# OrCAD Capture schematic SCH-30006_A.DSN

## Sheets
1 1. TITLE PAGE: title: FRDM33926PNBEVM; rev: A; company: Freescale Semiconductor; note: SCH-30006 PDF: SPF-30006; note: 6501 William Cannon Drive West; note: Austin, TX 78735-8598
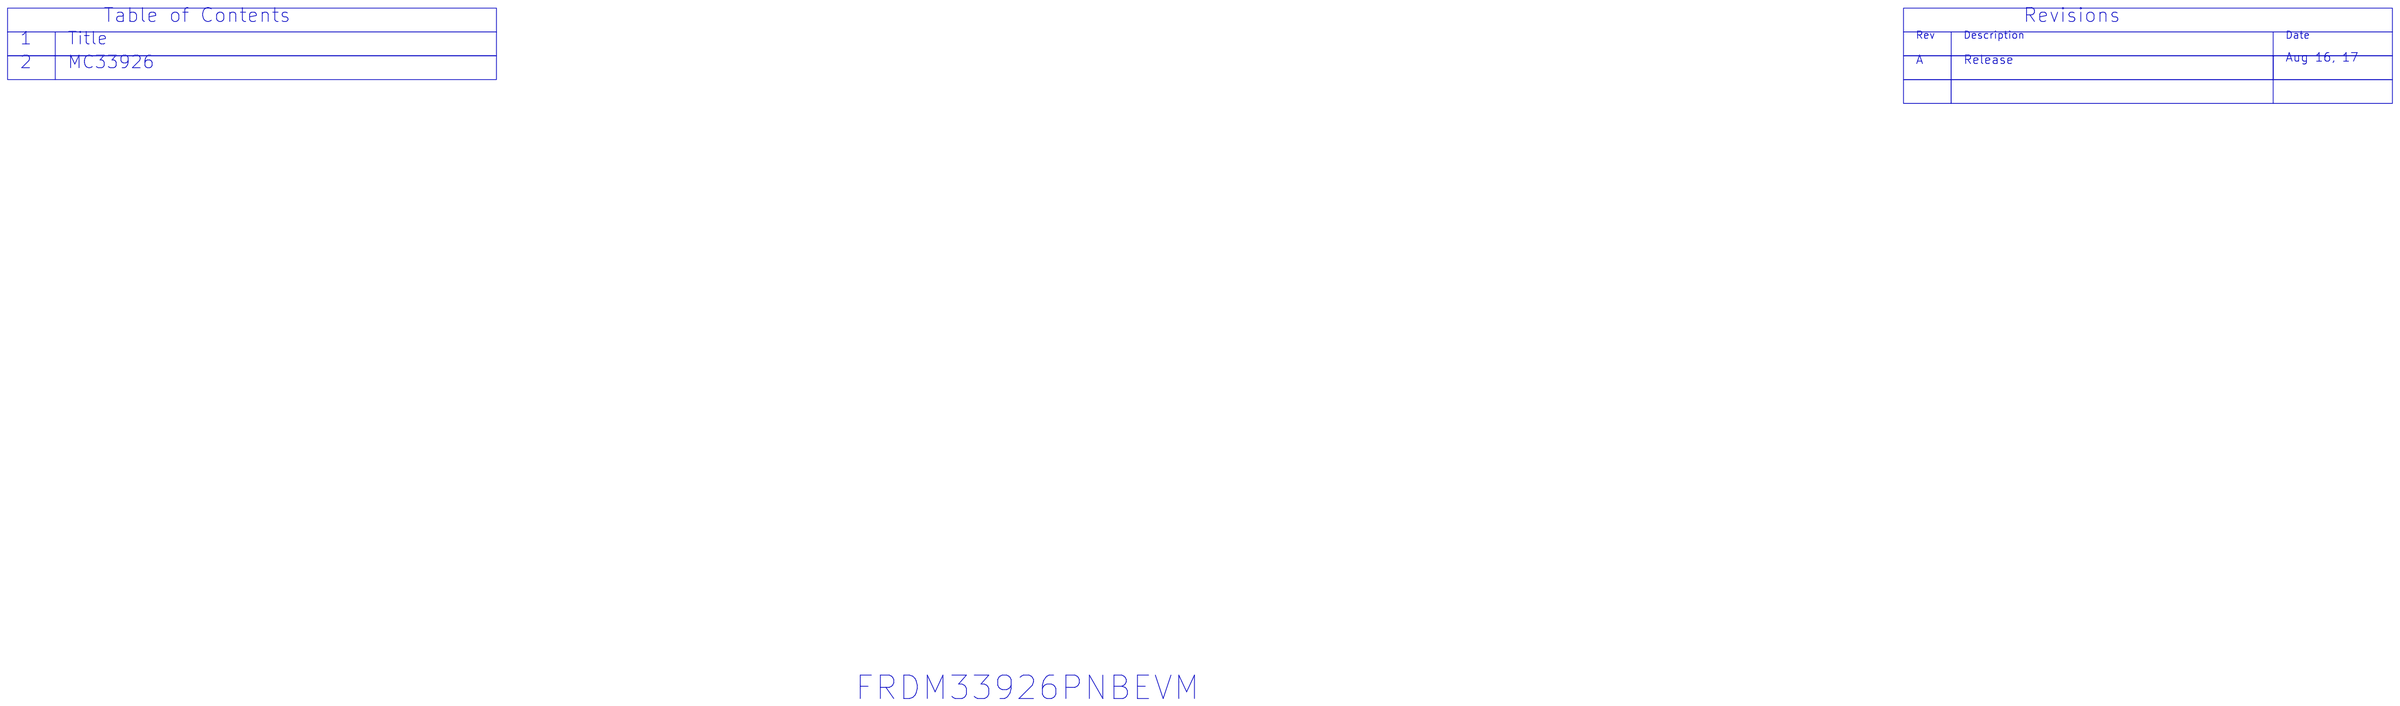
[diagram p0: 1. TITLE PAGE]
2 2. MC33926: size C
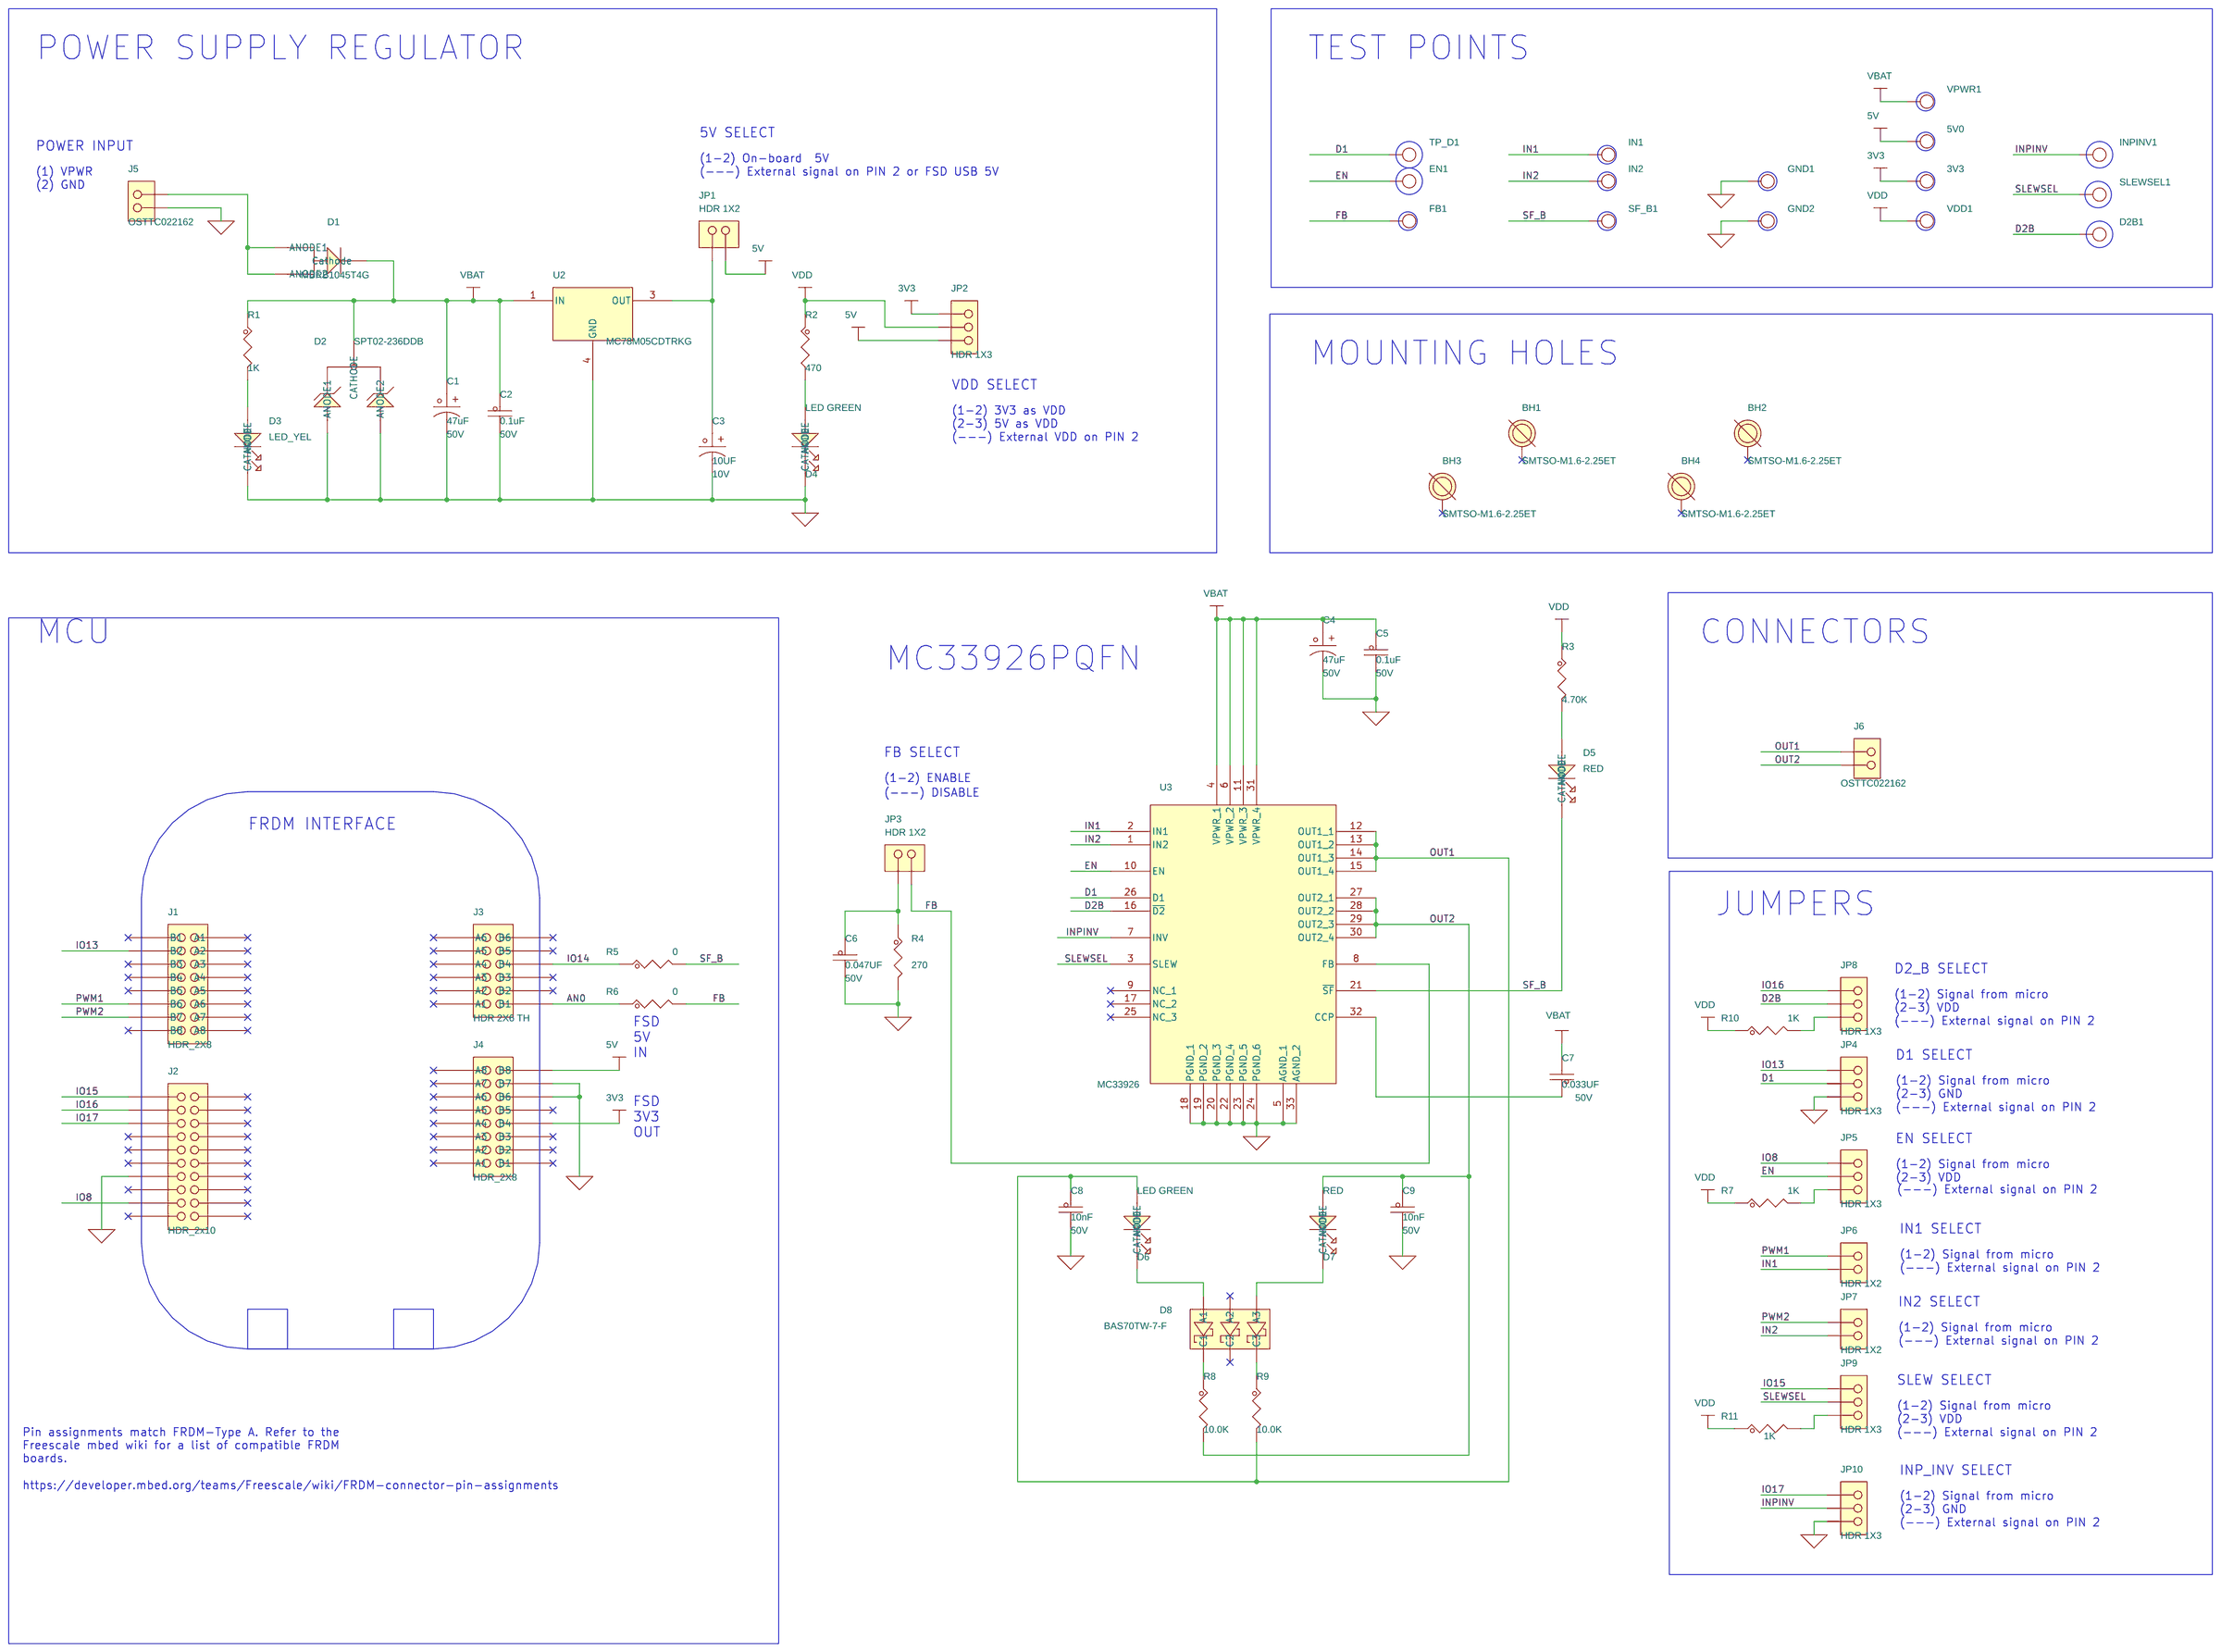
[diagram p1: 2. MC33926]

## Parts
3V3  TEST POINT RED  [TEST_LOOP]
5V0  TEST POINT RED  [TEST_LOOP]
BH1  SMTSO-M1.6-2.25ET  [MH194-116T]
BH2  SMTSO-M1.6-2.25ET  [MH194-116T]
BH3  SMTSO-M1.6-2.25ET  [MH194-116T]
BH4  SMTSO-M1.6-2.25ET  [MH194-116T]
C1  47uF  [cce10_3x10_3]
C2  0.1uF  [CC0603_OV]
C3  10UF  [CASE_A]
C4  47uF  [cce10_3x10_3]
C5  0.1uF  [CC0603_OV]
C6  0.047UF  [CC0805_OV]
C7  0.033UF  [CC0603_OV]
C8  10nF  [CC0603_OV]
C9  10nF  [CC0603_OV]
D1  MBRB1045T4G  [d2pak_b]
D2  SPT02-236DDB  [diode3_uqfn_sm]
D2B1  TEST POINT BLUE  [TEST_LOOP]
D3  LED_YEL  [LED_0603]
D4  LED GREEN  [LED_0603]
D5  RED  [0603LED]
D6  LED GREEN  [LED_0603]
D7  RED  [0603LED]
D8  BAS70TW-7-F  [sc70-6]
EN1  TEST POINT WHITE  [TEST_LOOP]
FB1  TEST POINT ORANGE  [TEST_LOOP]
GND1  TEST POINT BLACK  [TEST_LOOP]
GND2  TEST POINT BLACK  [TEST_LOOP]
IN1  TEST POINT BLUE  [TEST_LOOP]
IN2  TEST POINT BLUE  [TEST_LOOP]
INPINV1  TEST POINT BLUE  [TEST_LOOP]
J1  HDR_2X8  [HDR208]
J2  HDR_2x10  [hdr210]
J3  HDR 2X6 TH  [HDR206]
J4  HDR_2X8  [HDR208]
J5  OSTTC022162  [con2_tb_5p08_th_osttc]
J6  OSTTC022162  [con2_tb_5p08_th_osttc]
JP1  HDR 1X2  [HDR102]
JP2  HDR 1X3  [HDR103]
JP3  HDR 1X2  [HDR102]
JP4  HDR 1X3  [HDR103]
JP5  HDR 1X3  [HDR103]
JP6  HDR 1X2  [HDR102]
JP7  HDR 1X2  [HDR102]
JP8  HDR 1X3  [HDR103]
JP9  HDR 1X3  [HDR103]
JP10  HDR 1X3  [HDR103]
R1  1K  [RC0603_OV]
R2  470  [RC1206_OV]
R3  4.70K  [RC0603_OV]
R4  270  [RC0603_OV]
R5  0  [RC0603_OV]
R6  0  [RC0603_OV]
R7  1K  [RC0603_OV]
R8  10.0K  [RC0603_OV]
R9  10.0K  [RC0603_OV]
R10  1K  [RC0603_OV]
R11  1K  [RC0603_OV]
SF_B1  TEST POINT YELLOW  [TEST_LOOP]
SLEWSEL1  TEST POINT BLUE  [TEST_LOOP]
TP_D1  TEST POINT WHITE  [TEST_LOOP]
U2  MC78M05CDTRKG  [DPAK_CASE_369C-01]
U3  MC33926  [PQFN32_0P8_8X8_SLUG]
VDD1  TEST POINT RED  [TEST_LOOP]
VPWR1  TEST POINT RED  [TEST_LOOP]

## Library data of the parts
3V3 5V0 VDD1 VPWR1 = TestLoop: TEST POINT RED 40 MIL DRILL 180 MIL TH 109L; AGILE_PN: 210-75684; CAD_APPROVED: Yes; HEIGHT: 4.8 MM; MFG_NAME01: KEYSTONE ELECTRONICS; MFG_PN01: 5000; ROHS: Yes
BH1-BH4 = MOUNT_HOLE: FASTENER, STANDOFF M1.6 TH 2.25MM; AGILE_PN: 280-76628; CAD_APPROVED: Yes; HEIGHT: 2.35 MM; MFG_NAME01: SUZHOU HIGHBALL TEC; ROHS: Yes
C1 C4 = CAP_POL: CAP ALEL 47UF 50V 20% AUTO SMD; AGILE_PN: 150-79368; CAD_APPROVED: Yes; HEIGHT: 11MM; MFG_NAME01: Nichicon; MFG_PN01: UBC1H470MNS1GS; ROHS: Yes; Tolerance: 20%; VOLTAGE: 50V
C2 = CAP_NP: CAP CER 0.1uF 50V 5% X7R AEC-Q200 0603; AGILE_PN: 150-79363; CAD_APPROVED: Yes; FPLIST: CC0603_OV,CC0603,0603_CC; HEIGHT: 0.87MM; MFG_NAME01: Kemet; MFG_PN01: C0603C104J5RACAUTO; PRIORITY_PN: 021-00311; ROHS: Yes; Tolerance: 5%; VOLTAGE: 50V
C3 = CAP_POL: CAP TANT 10UF 10V 10% -- 3216-18; AGILE_PN: 150-30020; CAD_APPROVED: Yes; HEIGHT: 1.8mm; MFG_NAME01: VISHAY INTERTECHNOLOGY; MFG_PN01: 293D106X9010A2TE3; ROHS: Yes; Tolerance: 10%; VOLTAGE: 10V
C5 = CAP_NP: CAP CER 0.1uF 50V 5% X7R AEC-Q200 0603; AGILE_PN: 150-79363; CAD_APPROVED: Yes; FPLIST: CC0603_OV,CC0603,0603_CC; HEIGHT: 0.87MM; MFG_NAME01: Kemet; MFG_PN01: C0603C104J5RACAUTO; ROHS: Yes; Tolerance: 5%; VOLTAGE: 50V
C6 = CAP_NP: CAP CER 0.047UF 50V 5% X7R 0805; AGILE_PN: 150-77480; CAD_APPROVED: Yes; FPLIST: CC0805_OV,CC0805,0805_CC; HEIGHT: 0.88MM; MFG_NAME01: KEMET; MFG_PN01: C0805C473J5RAC; ROHS: Yes; Tolerance: 5%; VOLTAGE: 50V
C7 = CAP_NP: CAP CER 0.033UF 50V 5% X7R 0603; AGILE_PN: 150-30041; CAD_APPROVED: Yes; FPLIST: CC0603_OV,CC0603,0603_CC; HEIGHT: 0.86 MM; MFG_NAME01: AVX; MFG_PN01: 06035C333JAT2A; ROHS: Yes; Tolerance: 5%; VOLTAGE: 50V
C8 C9 = CAP_NP: CAP CER 0.01UF 50V 5% X7R 0603; AGILE_PN: 150-30087; CAD_APPROVED: Yes; FPLIST: CC0603_OV,CC0603,0603_CC; HEIGHT: 0.86 MM; MFG_NAME01: AVX; MFG_PN01: 06035C103JAT2A; ROHS: Yes; Tolerance: 5%; VOLTAGE: 50V
D1 = Diode_13A_4C: DIODE SCH PWR RECT 10A 45V D2PAK; AGILE_PN: 480-78796; CAD_APPROVED: Yes; HEIGHT: 4.83MM; MFG_NAME01: ON Semiconductor; ROHS: Yes
D2 = DZ_DUAL_CK_A1A2C: DIODE DUAL ARRAY 2A 6-36V uQFN-2L; AGILE_PN: 480-78841; CAD_APPROVED: Yes; HEIGHT: 0.8MM; MFG_NAME01: ST MICROELECTRONICS; ROHS: Yes
D2B1 IN1 IN2 INPINV1 SLEWSEL1 = TestLoop: TEST POINT BLUE 40 MIL DRILL 180 MIL TH 120L; AGILE_PN: 210-80627; CAD_APPROVED: Yes; HEIGHT: 4.7 MM; MFG_NAME01: Keystone Electronics; MFG_PN01: 5117; ROHS: Yes
D3 = LED: LED YEL SGL 25MA 0603; AGILE_PN: 370-76522; CAD_APPROVED: Yes; HEIGHT: 0.8MM; MFG_NAME01: DIALIGHT; MFG_PN01: 598-8040-107F; ROHS: Yes
D4 D6 = LED: LED GRN SGL 20MA 0603; AGILE_PN: 370-76565; CAD_APPROVED: Yes; HEIGHT: 0.67MM; MFG_NAME01: osram; MFG_PN01: LG L29K-G2J1-24-Z; ROHS: Yes
D5 D7 = LED: LED SM RED 0603 ROHS COMPLIANT; AGILE_PN: 370-30000; CAD_APPROVED: Yes; HEIGHT: 1.15mm; MFG_NAME01: FAIRCHILD; MFG_PN01: QTLP600CRTR; ROHS: Yes
D8 = BAS70TW: DIODE SCH TRIPLE 70MA 70V / 200MW SOT363; AGILE_PN: 480-76817; CAD_APPROVED: Yes; HEIGHT: 1.1 MM; MFG_NAME01: DIODES INC; ROHS: Yes
EN1 TP_D1 = TestLoop: TEST POINT WHITE 40 MIL DRILL 180 MIL TH 109L; AGILE_PN: 210-75685; CAD_APPROVED: Yes; HEIGHT: 4.8 MM; MFG_NAME01: KEYSTONE ELECTRONICS; MFG_PN01: 5002; ROHS: Yes
FB1 = TestLoop: TEST POINT ORANGE 40 MIL DRILL 180 MIL TH; AGILE_PN: 210-76025; CAD_APPROVED: Yes; HEIGHT: 4.8 mm; MFG_NAME01: Keystone Electronics; MFG_PN01: 5003; ROHS: Yes
GND1 GND2 = TestLoop: TEST POINT BLACK 40 MIL DRILL 180 MIL TH 109L; AGILE_PN: 210-75683; CAD_APPROVED: Yes; HEIGHT: 4.8mm; MFG_NAME01: KEYSTONE ELECTRONICS; MFG_PN01: 5001; ROHS: Yes
J1 J4 = CONN_HDR_8X2: HDR 2X8 TH 100MIL CTR 338H SN 100L; AGILE_PN: 210-80838; CAD_APPROVED: Yes; HEIGHT: 8.58MM; MFG_NAME01: SAMTEC; MFG_PN01: TSW-108-07-T-D; ROHS: Yes
J2 = CONN_HDR_10X2: HDR 2X10 TH 100MIL CTR 343H SN 100L; AGILE_PN: 210-80333; CAD_APPROVED: Yes; HEIGHT: 8.72MM; MFG_NAME01: SAMTEC; MFG_PN01: TSW-110-07-T-D; ROHS: Yes
J3 = CONN_HDR_6X2: HDR 2X6 TH 100MIL CTR 338H SN 100L; AGILE_PN: 210-80397; CAD_APPROVED: Yes; HEIGHT: 8.58MM; MFG_NAME01: SAMTEC; MFG_PN01: TSW-106-07-T-D; ROHS: Yes
J5 J6 = HDR-1X2: CON 1X2 TB 5.08MM SP 406H SN 138L; AGILE_PN: 210-80384; CAD_APPROVED: Yes; HEIGHT: 10.3MM; MFG_NAME01: ON-SHORE TECHNOLOGY; ROHS: Yes
JP1 JP3 JP6 JP7 = CONN_HDR_2X1: HDR 1X2 TH 100MIL SP 338H SN 100L; AGILE_PN: 210-80102; CAD_APPROVED: Yes; HEIGHT: 8.58MM; MFG_NAME01: SAMTEC; MFG_PN01: TSW-102-07-T-S; ROHS: Yes
JP2 JP4 JP5 JP8-JP10 = CONN_HDR_3X1: HDR 1x3 TH 100MIL SP 343H SN 100L; AGILE_PN: 210-80334; CAD_APPROVED: Yes; HEIGHT: 8.72MM; MFG_NAME01: SAMTEC; MFG_PN01: TSW-103-07-T-S; ROHS: Yes
R1 R7 R10 R11 = RES: RES -- 1K 1/4W 1% AEC-Q200 0603 ANTISURGE; AGILE_PN: 470-80639; CAD_APPROVED: Yes; FPLIST: RC0603_OV,RC0603,0603_CC; HEIGHT: 0.55MM; MFG_NAME01: ROHM; MFG_PN01: ESR03EZPF1001; ROHS: Yes; Tolerance: 1%
R2 = RES: RES MF 470 OHM 1/4W 5% AEC-Q200 1206; AGILE_PN: 470-75649; CAD_APPROVED: Yes; FPLIST: RC1206_OV,RC1206,1206_CC; HEIGHT: 0.71MM; MFG_NAME01: VISHAY INTERTECHNOLOGY; MFG_PN01: CRCW1206470RJNEA; ROHS: Yes; Tolerance: 5%
R3 = RES: RES MF 4.7K 1/4W 1% AEC-Q200 0603; AGILE_PN: 470-80817; CAD_APPROVED: Yes; FPLIST: RC0603_OV,RC0603,0603_CC; HEIGHT: 0.55 MM; MFG_NAME01: VISHAY INTERTECHNOLOGY; MFG_PN01: CRCW06034K70FKEAHP; ROHS: Yes; Tolerance: 1%
R4 = RES: RES MF 270 OHM 1/8W 1% AEC-Q200 0603; AGILE_PN: 470-81699; CAD_APPROVED: Yes; FPLIST: RC0603_OV,RC0603,0603_CC; HEIGHT: 0.55MM; MFG_NAME01: KOA SPEER; MFG_PN01: RK73H1JTTD2700F; ROHS: Yes; Temp_Range: -55&#8451; to 155&#8451;; Tolerance: 1%
R5 R6 = RES: RES MF ZERO OHM 1/10W -- AEC-Q200 0603; AGILE_PN: 470-75407; CAD_APPROVED: Yes; FPLIST: RC0603_OV,RC0603,R603-X2,0603_CC; HEIGHT: 0.6MM; MFG_NAME01: KOA SPEER; MFG_PN01: RK73Z1JTTD; ROHS: Yes; Tolerance: 1%
R8 R9 = RES: RES MF 10.0K 1/10W 1% 0603; AGILE_PN: 470-75422; CAD_APPROVED: Yes; FPLIST: RC0603_OV,RC0603,0603_CC; HEIGHT: 0.6MM; MFG_NAME01: YAGEO AMERICA; MFG_PN01: RC0603FR-0710KL; ROHS: Yes; Tolerance: 1%
SF_B1 = TestLoop: TEST POINT YELLOW 40 MIL DRILL 180 MIL TH; AGILE_PN: 210-76023; CAD_APPROVED: Yes; HEIGHT: 4.8 MM; MFG_NAME01: Keystone Electronics; MFG_PN01: 5004; ROHS: Yes
U2 = MC7805: IC LIN VREG LDO 5V 0.5A 35V DPAK; AGILE_PN: 315-80586; CAD_APPROVED: Yes; HEIGHT: 2.38MM; MFG_NAME01: ON Semiconductor; ROHS: Yes
U3 = MC33926: IC THROTTLE CONTROL H-BRIDGE 8.0-28V PQFN32; AGILE_PN: 330-21850; CAD_APPROVED: Yes; HEIGHT: 2.2MM; MFG_NAME01: FREESCALE SEMICONDUCTOR; MFG_PN01: MC33926PNB; ROHS: Yes

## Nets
3V3: 3V3.1(Pin1) J4.8(B4) JP2.1
5V: 5V0.1(Pin1) J4.16(B8) JP1.2 JP2.3
GND_SIGNAL: C1.2 C2.2 C3.2 C4.2 C5.2 C6.2 C8.2 C9.2 D2.1(ANODE1) D2.2(ANODE2) D3.C(CATHODE) D4.C(CATHODE) GND1.1(Pin1) GND2.1(Pin1) J2.14 J4.12(B6) J4.14(B7) J5.2 JP4.3 JP10.3 R4.2 U2.4(GND) U3.5(AGND_1) U3.18(PGND_1) U3.19(PGND_2) U3.20(PGND_3) U3.22(PGND_4) U3.23(PGND_5) U3.24(PGND_6) U3.33(AGND_2)
VBAT: C1.1 C2.1 C4.1 C5.1 C7.2 D1.4(Cathode) D2.3(CATHODE) R1.1 U2.1(IN) U3.4(VPWR_1) U3.6(VPWR_2) U3.11(VPWR_3) U3.31(VPWR_4) VPWR1.1(Pin1)
VDD: JP2.2 R2.1 R3.1 R7.1 R10.1 R11.1 VDD1.1(Pin1)
AN0: J3.2(B1) R6.1
D1: JP4.2 TP_D1.1(Pin1) U3.26(D1)
D2B: D2B1.1(Pin1) JP8.2 U3.16(~{D2})
EN: EN1.1(Pin1) JP5.2 U3.10(EN)
FB: FB1.1(Pin1) JP3.2 R6.2 U3.8(FB)
IN1: IN1.1(Pin1) JP6.2 U3.2(IN1)
IN2: IN2.1(Pin1) JP7.2 U3.1(IN2)
INPINV: INPINV1.1(Pin1) JP10.2 U3.7(INV)
IO8: J2.18 JP5.1
IO13: J1.4(B2) JP4.1
IO14: J3.8(B4) R5.1
IO15: J2.2 JP9.1
IO16: J2.4 JP8.1
IO17: J2.6 JP10.1
OUT1: C8.1 D6.A(ANODE) J6.1 R9.2 U3.12(OUT1_1) U3.13(OUT1_2) U3.14(OUT1_3) U3.15(OUT1_4)
OUT2: C9.1 D7.A(ANODE) J6.2 R8.2 U3.27(OUT2_1) U3.28(OUT2_2) U3.29(OUT2_3) U3.30(OUT2_4)
PWM1: J1.12(B6) JP6.1
PWM2: J1.14(B7) JP7.1
SF_B: D5.C(CATHODE) R5.2 SF_B1.1(Pin1) U3.21(~{SF})
SLEWSEL: JP9.2 SLEWSEL1.1(Pin1) U3.3(SLEW)
N16404454: D3.A(ANODE) R1.2
N16404466: D1.1(ANODE1) D1.3(ANODE2) J5.1
N16404596: C3.1 JP1.1 U2.3(OUT)
N16404846: JP5.3 R7.2
N16404992: C6.1 JP3.1 R4.1
N16405180: D7.C(CATHODE) D8.3(A3)
N16405200: D6.C(CATHODE) D8.1(A1)
N16405574: D4.A(ANODE) R2.2
N16406148: D8.4(C3) R9.1
N16406152: D8.6(C1) R8.1
N16409368: D5.A(ANODE) R3.2
N16478318: JP8.3 R10.2
N16492232: C7.1 U3.32(CCP)
N16695009: JP9.3 R11.2

Not connected (* = marked no-connect by the designer): BH1 1*; BH2 1*; BH3 1*; BH4 1*; D8 2(A2)* 5(C2)*; J1 1(A1)* 2(B1)* 3(A2)* 5(A3)* 6(B3)* 7(A4)* 8(B4)* 9(A5)* 10(B5)* 11(A6)* 13(A7)* 15(A8)* 16(B8)*; J2 1* 3* 5* 7* 8* 9* 10* 11* 12* 13* 15* 16* 17* 19* 20*; J3 1(A1)* 3(A2)* 4(B2)* 5(A3)* 6(B3)* 7(A4)* 9(A5)* 10(B5)* 11(A6)* 12(B6)*; J4 1(A1)* 2(B1)* 3(A2)* 4(B2)* 5(A3)* 6(B3)* 7(A4)* 9(A5)* 10(B5)* 11(A6)* 13(A7)* 15(A8)*; U3 9(NC_1)* 17(NC_2)* 25(NC_3)*

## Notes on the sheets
sheet 1
- Table of Contents
- Revisions
- 1
- Title
- Rev
- Description
- Date
- 2
- MC33926
- A
- Release
- Aug 16, 17
- FRDM33926PNBEVM
sheet 2
- POWER SUPPLY REGULATOR
- TEST POINTS
- 5V SELECT
- POWER INPUT
- (1) VPWR
- (---) External signal on PIN 2 or FSD USB 5V
- (1-2) On-board  5V
- (2) GND
- MOUNTING HOLES
- VDD SELECT
- (1-2) 3V3 as VDD
- (---) External VDD on PIN 2
- (2-3) 5V as VDD
- MCU
- CONNECTORS
- MC33926PQFN
- FB SELECT
- (1-2) ENABLE
- (---) DISABLE
- FRDM INTERFACE
- JUMPERS
- D2_B SELECT
- (1-2) Signal from micro
- (2-3) VDD
- FSD
  5V
  IN
- (---) External signal on PIN 2
- D1 SELECT
- (1-2) Signal from micro
- (2-3) GND
- FSD
  3V3
  OUT
- (---) External signal on PIN 2
- EN SELECT
- (1-2) Signal from micro
- (2-3) VDD
- (---) External signal on PIN 2
- IN1 SELECT
- (---) External signal on PIN 2
- (1-2) Signal from micro
- IN2 SELECT
- (1-2) Signal from micro
- (---) External signal on PIN 2
- SLEW SELECT
- (1-2) Signal from micro
- (2-3) VDD
- Pin assignments match FRDM-Type A. Refer to the
  Freescale mbed wiki for a list of compatible FRDM
  boards.
- (---) External signal on PIN 2
- INP_INV SELECT
- https://developer.mbed.org/teams/Freescale/wiki/FRDM-connector-pin-assignments
- (1-2) Signal from micro
- (2-3) GND
- (---) External signal on PIN 2
